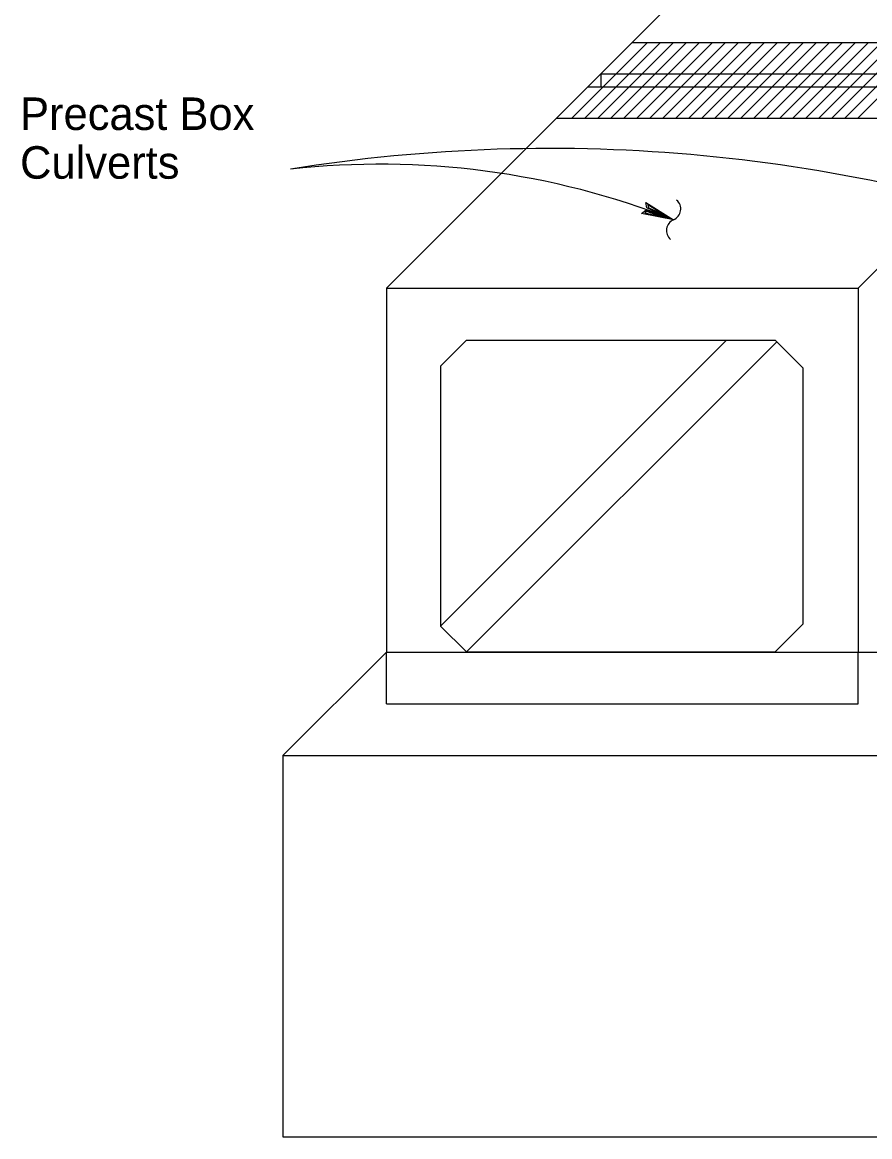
# Model space of a CAD drawing. Extents: x 0 to 2.83, y -0.03 to 1.83.
# Drawn here: x 1.6293 to 1.9689, y 1.0539 to 1.5005 of the extents above; entities that cross this region are included whole.
import ezdxf

# ---------------------------------------------------------------- set-up
doc = ezdxf.new("R2010")
doc.units = 0
for name, color, linetype in [('50', 7, 'Continuous'), ('55', 7, 'Continuous'), ('57', 7, 'Continuous'), ('Default', 7, 'Continuous')]:
    doc.layers.add(name, color=color, linetype=linetype)

msp = doc.modelspace()

# ---------------------------------------------------------------- linework, layer by layer
at = {"layer": '50'}
for p, q in [((1.861178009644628, 1.4799350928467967), (1.9418897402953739, 1.5606468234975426)), ((1.7752579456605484, 1.3940150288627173), (1.8559696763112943, 1.4747267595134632)), ((1.9642438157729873, 1.3940150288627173), (2.0449555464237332, 1.4747267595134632)), ((1.7752579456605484, 1.3940150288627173), (1.7752579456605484, 1.2481651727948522)), ((1.7752579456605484, 1.3940150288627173), (1.9642438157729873, 1.3940150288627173)), ((1.9642438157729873, 1.3940150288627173), (1.9642438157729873, 1.2481651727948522)), ((1.7969593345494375, 1.258598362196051), (1.9115426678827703, 1.373181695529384)), ((1.7969593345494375, 1.362765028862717), (1.807376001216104, 1.3731816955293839)), ((1.8073760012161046, 1.373181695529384), (1.9310074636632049, 1.373181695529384)), ((1.807376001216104, 1.2481816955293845), (1.9316917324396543, 1.3724974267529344)), ((1.9310074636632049, 1.373181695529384), (1.9421083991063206, 1.3620807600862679)), ((1.9421083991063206, 1.3620807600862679), (1.9421083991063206, 1.2592826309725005)), ((1.7969593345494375, 1.258598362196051), (1.807376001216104, 1.2481816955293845)), ((1.9310074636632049, 1.2481816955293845), (1.9421083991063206, 1.2592826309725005)), ((1.7752579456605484, 1.2481651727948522), (2.1584380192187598, 1.2481651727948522)), ((1.807376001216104, 1.2481816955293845), (1.9310074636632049, 1.2481816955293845))]:
    msp.add_line(p, q, dxfattribs=at)
at = {"layer": '55'}
for points in [[(1.8903221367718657, 1.4213851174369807), (1.8774277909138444, 1.4239480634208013), (1.8791913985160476, 1.4252579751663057), (1.8875199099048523, 1.4225021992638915), (1.8795389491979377, 1.4262048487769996), (1.8791590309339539, 1.428371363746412), (1.8903019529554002, 1.4214020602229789)], [(1.8856299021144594, 1.4226402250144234), (1.879626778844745, 1.4247273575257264), (1.8787207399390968, 1.4241357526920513), (1.888973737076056, 1.4219183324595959), (1.8799724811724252, 1.4273238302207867), (1.8802351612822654, 1.4262431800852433), (1.885815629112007, 1.423812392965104)]]:
    msp.add_lwpolyline(points, dxfattribs=at)
for centre, radius, start, end in [((1.8406540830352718, 0.7977381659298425), 0.6522386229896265, 69.99222012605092, 99.15879297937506), ((1.772778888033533, 1.1225429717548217), 0.3211361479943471, 68.53330993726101, 96.42615989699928), ((1.8884569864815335, 1.425722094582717), 0.004697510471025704, 293.12597883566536, 49.532048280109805), ((1.8921469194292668, 1.4170820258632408), 0.004697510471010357, 113.12597883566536, 229.5320482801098)]:
    msp.add_arc(centre, radius, start, end, dxfattribs=at)
at = {"layer": 'Default'}
for p, q in [((1.8798608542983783, 1.492494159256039), (1.84953438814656, 1.462167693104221)), ((1.8850691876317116, 1.492494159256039), (1.8547427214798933, 1.462167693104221)), ((1.8902775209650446, 1.492494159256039), (1.8599510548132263, 1.462167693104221)), ((1.87373707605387, 1.4924941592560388), (1.861178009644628, 1.4799350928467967)), ((1.895485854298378, 1.492494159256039), (1.8651593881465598, 1.462167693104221)), ((1.9006941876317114, 1.492494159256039), (1.870367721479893, 1.462167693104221)), ((1.8737370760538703, 1.492494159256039), (2.0626171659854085, 1.492494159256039)), ((1.9059025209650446, 1.492494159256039), (1.8755760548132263, 1.462167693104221)), ((1.9111108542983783, 1.492494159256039), (1.88078438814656, 1.462167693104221)), ((1.9163191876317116, 1.492494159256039), (1.8859927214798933, 1.462167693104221)), ((1.9215275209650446, 1.492494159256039), (1.8912010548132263, 1.462167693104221)), ((1.926735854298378, 1.492494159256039), (1.8964093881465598, 1.462167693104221)), ((1.9319441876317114, 1.492494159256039), (1.901617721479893, 1.462167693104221)), ((1.9371525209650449, 1.492494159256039), (1.9068260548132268, 1.462167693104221)), ((1.9423608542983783, 1.492494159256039), (1.91203438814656, 1.462167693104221)), ((1.9475691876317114, 1.492494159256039), (1.917242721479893, 1.462167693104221)), ((1.9527775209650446, 1.492494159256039), (1.9224510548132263, 1.462167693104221)), ((1.957985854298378, 1.492494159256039), (1.9276593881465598, 1.462167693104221)), ((1.9631941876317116, 1.492494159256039), (1.9328677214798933, 1.462167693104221)), ((1.9684025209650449, 1.492494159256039), (1.9380760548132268, 1.462167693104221)), ((1.973610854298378, 1.492494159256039), (1.9432843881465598, 1.462167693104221)), ((1.9788191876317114, 1.492494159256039), (1.948492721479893, 1.462167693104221)), ((1.9840275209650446, 1.492494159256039), (1.9537010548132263, 1.462167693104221)), ((1.989235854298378, 1.492494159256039), (1.9589093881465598, 1.462167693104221)), ((1.9944441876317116, 1.492494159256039), (1.9641177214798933, 1.462167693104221)), ((1.8611780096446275, 1.4799350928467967), (1.8434106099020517, 1.462167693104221)), ((1.861178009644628, 1.4799350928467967), (2.0501638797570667, 1.4799350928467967)), ((1.861178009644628, 1.4799350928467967), (1.861178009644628, 1.474726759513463)), ((1.8559696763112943, 1.4747267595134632), (2.0449555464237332, 1.4747267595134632)), ((1.8434106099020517, 1.462167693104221), (2.0322906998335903, 1.462167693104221)), ((1.7969593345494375, 1.362765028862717), (1.7969593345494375, 1.258598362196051)), ((1.7752579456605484, 1.2481651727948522), (1.7336947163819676, 1.2066684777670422)), ((1.7752579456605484, 1.2481651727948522), (2.1584380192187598, 1.2481651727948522)), ((1.7752579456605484, 1.2273483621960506), (1.7752579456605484, 1.2481651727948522)), ((1.9642438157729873, 1.2273483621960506), (1.9642438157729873, 1.2481651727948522)), ((1.7752579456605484, 1.2273483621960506), (1.9642438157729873, 1.2273483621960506)), ((1.7336947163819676, 1.2066684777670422), (2.1169912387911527, 1.2066684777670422)), ((1.7336947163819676, 1.2066684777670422), (1.7336947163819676, 1.0539290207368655)), ((1.7336947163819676, 1.0539290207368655), (2.1169912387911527, 1.0539290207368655))]:
    msp.add_line(p, q, dxfattribs=at)

# ---------------------------------------------------------------- texts
at = {"layer": '57'}
for s, p in [('Precast Box', (1.628460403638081, 1.4573872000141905)), ('Culverts', (1.628460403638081, 1.4378559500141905))]:
    msp.add_text(s, height=0.013020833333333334, dxfattribs=at).set_placement(p)

doc.saveas('drawing.dxf')
